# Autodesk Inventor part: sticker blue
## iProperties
Shininess: 64.0
Length Units: 11269
Angle Units: 11279
Time Units: 11290
Mass Units: 11283
Length Display Precision: 3
Angle Display Precision: 2
Compacted: True
Part Number: sticker blue
Document SubType Name: Modeling
Created: 2004-10
Material: Standard
Designer: W. Holzwarth
Manufacturer: Standard
Standards Organization: Custom
Density: 0.0
Volumn: 0.0
Area: 0.0
PropertySet Name: Model Information
Control State: 0
Master: False
Checked Out: False
Author: W. Holzwarth
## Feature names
1. Basis1
